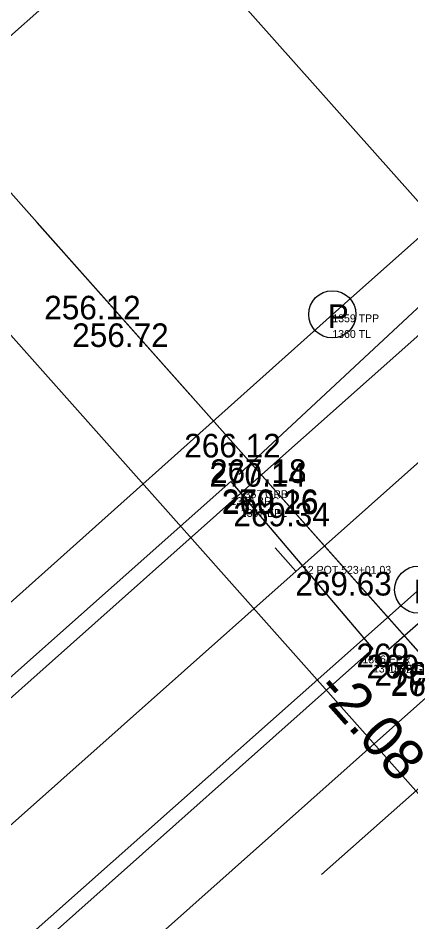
# Model space of a CAD drawing. Extents: x 49683 to 58852, y 49525 to 54803.
# Drawn here: x 53855 to 53904.9, y 51834.7 to 51949.6 of the extents above; entities that cross this region are included whole.
import ezdxf

# ---------------------------------------------------------------- set-up
doc = ezdxf.new("R2010")
doc.units = 0
for name, color, linetype in [('Level 1', 7, 'Continuous'), ('Level 11', 7, 'Continuous'), ('Level 13', 7, 'Continuous'), ('Level 15', 7, 'Continuous'), ('Level 20', 7, 'Continuous'), ('Level 3', 7, 'Continuous'), ('Level 32', 7, 'Continuous'), ('Level 5', 7, 'Continuous'), ('Level 50', 7, 'Continuous'), ('Level 51', 7, 'Continuous'), ('Level 53', 7, 'Continuous'), ('Level 55', 7, 'Continuous'), ('Level 57', 7, 'Continuous'), ('Level 59', 7, 'Continuous'), ('Level 61', 7, 'Continuous'), ('Level 63', 7, 'Continuous'), ('Level 7', 7, 'Continuous'), ('Level 9', 7, 'Continuous')]:
    doc.layers.add(name, color=color, linetype=linetype)

# ---------------------------------------------------------------- blocks, each defined once
blk = doc.blocks.new('TPP')
at = {"layer": 'Level 9'}
blk.add_circle((0, 0), 3, dxfattribs=at)
blk.add_text('P', height=3, dxfattribs=at).set_placement((-0.59, -1.73))

msp = doc.modelspace()

# ---------------------------------------------------------------- linework, layer by layer
at = {"layer": 'Level 1'}
for p, q in [((52544.81, 50683.3), (55534.58, 53340.86)), ((53890.28, 51879.27), (53887.62, 51882.26))]:
    msp.add_line(p, q, dxfattribs=at)
at = {"layer": 'Level 11'}
for p, q in [((53894.91, 51911.93), (54324.2, 52292.62)), ((53424.49, 51490.93), (53894.91, 51911.93))]:
    msp.add_line(p, q, dxfattribs=at)
at = {"layer": 'Level 13'}
msp.add_line((53573.51, 51698.05), (53897.28, 51985.83), dxfattribs=at)
at = {"layer": 'Level 15'}
msp.add_line((53460.73, 51466.68), (53909.18, 51865.3), dxfattribs=at)
at = {"layer": 'Level 20'}
msp.add_line((53893.55, 51840.7), (54172.47, 52088.62), dxfattribs=at)
at = {"layer": 'Level 3'}
for p, q in [((53883.27, 51889.18), (54069.54, 52054.72)), ((53898.74, 51870.57), (54083.39, 52035.12)), ((53434.09, 51489.84), (53883.27, 51889.18)), ((53449.72, 51471.81), (53898.74, 51870.57))]:
    msp.add_line(p, q, dxfattribs=at)
at = {"layer": 'Level 5'}
for p, q in [((53432.56, 51491.2), (53881.99, 51890.68)), ((53881.99, 51890.68), (53900.07, 51869.4)), ((53900.07, 51869.4), (53451.19, 51470.16))]:
    msp.add_line(p, q, dxfattribs=at)
at = {"layer": 'Level 50'}
for p, q in [((53872.47, 51963.79), (54031.92, 51784.41)), ((53824.14, 51960.97), (54023.45, 51736.74)), ((53835.1, 51930.57), (53994.55, 51751.19))]:
    msp.add_line(p, q, dxfattribs=at)
at = {"layer": 'Level 53'}
msp.add_line((53857.36, 51923.59), (53990.23, 51774.11), dxfattribs=at)
at = {"layer": 'Level 7'}
for p, q in [((53908.49, 51915.3), (53883.02, 51891.57)), ((53902.07, 51869.33), (53922.85, 51887.66))]:
    msp.add_line(p, q, dxfattribs=at)

# ---------------------------------------------------------------- block references
at = {"layer": 'Level 9'}
for p in [(53894.91, 51911.93), (53905.83, 51876.92)]:
    msp.add_blockref('TPP', p, dxfattribs=at)

# ---------------------------------------------------------------- texts
at = {"layer": 'Level 32'}
for s, p in [('256.12', (53858.28, 51911.29)), ('256.72', (53861.84, 51907.78)), ('266.12', (53876.08, 51893.74)), ('267.18', (53879.36, 51890.5)), ('270.14', (53879.28, 51890.02)), ('270.16', (53880.86, 51886.67)), ('269.26', (53880.88, 51886.53)), ('269.34', (53882.32, 51884.98)), ('269.63', (53890.2, 51876.18)), ('269.36', (53897.96, 51867.07)), ('269.28', (53899.25, 51865.65)), ('270.20', (53900.25, 51864.74)), ('270.19', (53902.35, 51863.57)), ('267.11', (53902.35, 51863.41))]:
    msp.add_text(s, height=3, dxfattribs=at).set_placement(p)
at = {"layer": 'Level 51'}
msp.add_text('12 POT 523+01.03', height=1, dxfattribs=at).set_placement((53891.05, 51878.95))
at = {"layer": 'Level 53'}
for s, p in [('1367 EPL', (53883.27, 51886.18)), ('1366 EPR', (53898.74, 51867.57))]:
    msp.add_text(s, height=1, dxfattribs=at).set_placement(p)
at = {"layer": 'Level 55'}
for s, p in [('1349 BRC', (53881.99, 51887.68)), ('1350 BRC', (53900.07, 51866.4))]:
    msp.add_text(s, height=1, dxfattribs=at).set_placement(p)
at = {"layer": 'Level 57'}
for s, p in [('1357 GRB', (53883.02, 51888.57)), ('1352 GRA', (53902.07, 51866.33))]:
    msp.add_text(s, height=1, dxfattribs=at).set_placement(p)
at = {"layer": 'Level 59'}
msp.add_text('1359 TPP', height=1, dxfattribs=at).set_placement((53894.91, 51910.93))
at = {"layer": 'Level 61'}
msp.add_text('1360 TL', height=1, dxfattribs=at).set_placement((53894.91, 51908.93))
at = {"layer": 'Level 63'}
msp.add_text('-2.08', height=5.25, rotation=311.6335, dxfattribs=at).set_placement((53892.61, 51864.12))

doc.saveas('drawing.dxf')
